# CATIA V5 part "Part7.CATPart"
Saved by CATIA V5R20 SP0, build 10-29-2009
Part number: Part7
Bounding box of the stored display mesh (mm): x -150 to 400, y -129.814 to 379.814, z -80 to 80
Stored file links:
  E:\新建文件夹 (2)\Part7.CATPart
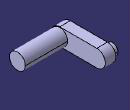
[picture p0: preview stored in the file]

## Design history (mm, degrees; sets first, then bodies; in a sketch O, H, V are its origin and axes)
Body1 (main body)
  Sketch1 on yz-plane, origin (0, 0, 0), H (0, 1, 0), V (0, 0, 1)
    arc A1 centre (300, 0) radius 80 from (300, -80) to (300, 80) ccw
    point P1 (300, 0)
    line L1 (300, 80) -> (-50, 80)
    line L2 (-50, -80) -> (300, -80)
    arc A2 centre (-50, 0) radius 80 from (-50, 80) to (-50, -80) ccw
    point P6 (-50, 0)
    coincidence: P1 H, P6 H
    tangency: L1 A1, L2 A1, A2 L1
  Pad1: profile Sketch1, direction (-1, 0, 0), length 100
  Sketch2 on end face of Pad1, origin (-100, 0, 0), H (0, -1, 0), V (0, 0, 1)
    circle A1 centre (-300, 0) radius 50
    point P1 (-300, 0)
    coincidence: P1 H
  Pad2: profile Sketch2, direction (-1, 0, 0), length 50
  Sketch3 on start face of Pad1, origin (0, 0, 0), H (0, 1, 0), V (0, 0, 1)
    point P1 (0, 75)
    circle A1 centre (-50, 0) radius 75
    point P2 (-50, 0)
    coincidence: P2 H
  Pad3: profile Sketch3, direction (1, 0, 0), length 400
